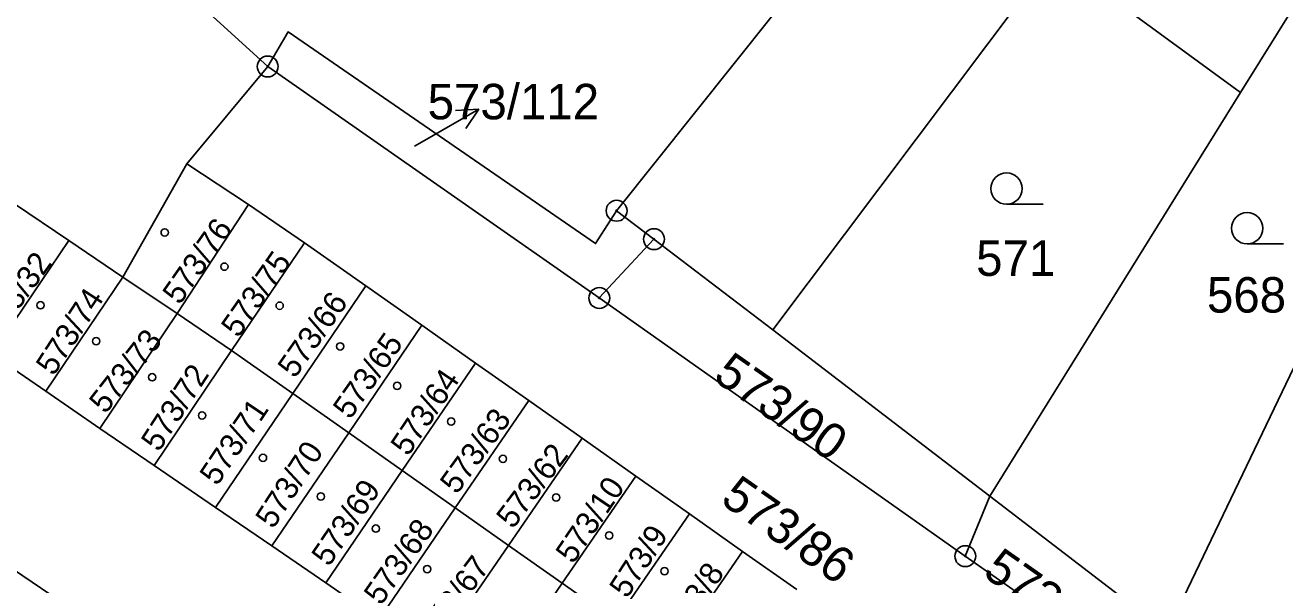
# Model space of a CAD drawing. Extents: x -776701 to -776081, y -974398 to -973771.
# Drawn here: x -776402.9 to -776342.5, y -974028.3 to -974001.5 of the extents above; entities that cross this region are included whole.
import ezdxf

# ---------------------------------------------------------------- set-up
doc = ezdxf.new("R2010")
doc.units = 0
for name, color, linetype in [('Hranice parcel', 7, 'Continuous'), ('Parcelní čísla', 7, 'Continuous'), ('Pop  PČ popisy', 7, 'Continuous'), ('Značky bodu BP', 7, 'Continuous'), ('Značky budov', 7, 'Continuous'), ('Značky kultur', 7, 'Continuous')]:
    doc.layers.add(name, color=color, linetype=linetype)

msp = doc.modelspace()

# ---------------------------------------------------------------- linework, layer by layer
at = {"layer": 'Hranice parcel'}
for p, q in [((-776391.25, -974003.46), (-776398.4, -973996.95)), ((-776353.58, -973998.16), (-776367.05, -974016.08)), ((-776353.58, -973998.16), (-776344.63, -974004.7)), ((-776395.13, -974008.13), (-776391.25, -974003.46)), ((-776375.36, -974014.55), (-776391.25, -974003.46)), ((-776344.63, -974004.7), (-776356.65, -974024.04)), ((-776398.19, -974013.55), (-776395.13, -974008.13)), ((-776392.17, -974010.07), (-776395.13, -974008.13)), ((-776403.38, -974010.04), (-776400.78, -974011.8)), ((-776392.17, -974010.07), (-776395.59, -974015.3)), ((-776389.48, -974011.9), (-776392.17, -974010.07)), ((-776374.53, -974010.37), (-776372.74, -974011.73)), ((-776348.16, -974030.54), (-776338.84, -974011.12)), ((-776404.47, -974017.25), (-776400.78, -974011.8)), ((-776400.78, -974011.8), (-776398.19, -974013.55)), ((-776389.48, -974011.9), (-776392.99, -974017.06)), ((-776386.55, -974013.97), (-776389.48, -974011.9)), ((-776372.74, -974011.73), (-776375.36, -974014.55)), ((-776372.74, -974011.73), (-776367.05, -974016.08)), ((-776398.19, -974013.55), (-776401.88, -974019.02)), ((-776395.59, -974015.3), (-776398.19, -974013.55)), ((-776386.55, -974013.97), (-776390.05, -974019.13)), ((-776383.87, -974015.86), (-776386.55, -974013.97)), ((-776357.82, -974026.92), (-776375.36, -974014.55)), ((-776395.59, -974015.3), (-776399.29, -974020.8)), ((-776392.99, -974017.06), (-776395.59, -974015.3)), ((-776383.87, -974015.86), (-776387.37, -974021.01)), ((-776381.29, -974017.67), (-776383.87, -974015.86)), ((-776367.05, -974016.08), (-776356.65, -974024.04)), ((-776392.99, -974017.06), (-776396.69, -974022.57)), ((-776392.99, -974017.06), (-776390.05, -974019.13)), ((-776404.47, -974017.25), (-776401.88, -974019.02)), ((-776381.29, -974017.67), (-776384.81, -974022.82)), ((-776378.74, -974019.46), (-776381.29, -974017.67)), ((-776401.88, -974019.02), (-776399.29, -974020.8)), ((-776390.05, -974019.13), (-776393.75, -974024.59)), ((-776390.05, -974019.13), (-776387.37, -974021.01)), ((-776378.74, -974019.46), (-776382.26, -974024.61)), ((-776376.18, -974021.27), (-776378.74, -974019.46)), ((-776399.29, -974020.8), (-776396.69, -974022.57)), ((-776387.37, -974021.01), (-776391.06, -974026.43)), ((-776387.37, -974021.01), (-776384.81, -974022.82)), ((-776376.18, -974021.27), (-776379.71, -974026.41)), ((-776373.61, -974023.08), (-776376.18, -974021.27)), ((-776396.69, -974022.57), (-776393.75, -974024.59)), ((-776384.81, -974022.82), (-776388.47, -974028.2)), ((-776384.81, -974022.82), (-776382.26, -974024.61)), ((-776373.61, -974023.08), (-776377.14, -974028.21)), ((-776371.04, -974024.89), (-776373.61, -974023.08)), ((-776357.82, -974026.92), (-776356.65, -974024.04)), ((-776356.65, -974024.04), (-776348.16, -974030.54)), ((-776393.75, -974024.59), (-776391.06, -974026.43)), ((-776382.26, -974024.61), (-776385.91, -974029.95)), ((-776382.26, -974024.61), (-776379.71, -974026.41)), ((-776371.04, -974024.89), (-776374.57, -974030.02)), ((-776368.49, -974026.69), (-776371.04, -974024.89)), ((-776391.06, -974026.43), (-776388.47, -974028.2)), ((-776379.71, -974026.41), (-776383.35, -974031.71)), ((-776379.71, -974026.41), (-776377.14, -974028.21)), ((-776368.49, -974026.69), (-776372.03, -974031.81)), ((-776365.9, -974028.51), (-776368.49, -974026.69)), ((-776348.94, -974033.12), (-776357.82, -974026.92)), ((-776400.79, -974029.35), (-776403.43, -974027.56)), ((-776388.47, -974028.2), (-776385.91, -974029.95)), ((-776380.76, -974033.48), (-776377.14, -974028.21)), ((-776377.14, -974028.21), (-776374.57, -974030.02))]:
    msp.add_line(p, q, dxfattribs=at)
for points in [[(-776337.75, -973970.3), (-776338.32, -973970.69), (-776348.3, -973977.53), (-776374.53, -974010.37)], [(-776336.89, -973994.45), (-776339.24, -973996.03), (-776344.63, -974004.7)], [(-776391.25, -974003.46), (-776390.27, -974001.8), (-776375.54, -974011.94), (-776374.53, -974010.37)]]:
    msp.add_lwpolyline(points, dxfattribs=at)
at = {"layer": 'Pop  PČ popisy'}
for p, q in [((-776383.73, -974007), (-776381.131, -974005.5)), ((-776381.131, -974005.5), (-776382.249, -974005.567)), ((-776381.131, -974005.5), (-776381.748, -974006.434)), ((-776384.22, -974007.28), (-776383.73, -974007))]:
    msp.add_line(p, q, dxfattribs=at)
at = {"layer": 'Značky bodu BP'}
for centre, radius in [((-776391.25, -974003.46), 0.5), ((-776391.25, -974003.46), 0.0303), ((-776374.53, -974010.37), 0.5), ((-776374.53, -974010.37), 0.0303), ((-776372.74, -974011.73), 0.5), ((-776372.74, -974011.73), 0.0303), ((-776375.36, -974014.55), 0.5), ((-776375.36, -974014.55), 0.0303), ((-776357.82, -974026.92), 0.5), ((-776357.82, -974026.92), 0.0303)]:
    msp.add_circle(centre, radius, dxfattribs=at)
at = {"layer": 'Značky budov'}
for centre in [(-776396.187, -974011.409), (-776393.327, -974013.049), (-776402.137, -974014.899), (-776390.677, -974014.919), (-776399.467, -974016.619), (-776387.777, -974016.869), (-776396.787, -974018.349), (-776385.047, -974018.759), (-776394.397, -974020.179), (-776382.457, -974020.469), (-776391.477, -974022.209), (-776379.977, -974022.259), (-776388.707, -974024.059), (-776377.427, -974024.109), (-776386.067, -974025.599), (-776374.887, -974025.929), (-776383.607, -974027.539), (-776372.237, -974027.639)]:
    msp.add_circle(centre, 0.175, dxfattribs=at)
at = {"layer": 'Značky kultur'}
for p, q in [((-776355.843, -974010.06), (-776354.093, -974010.06)), ((-776344.313, -974011.96), (-776342.563, -974011.96))]:
    msp.add_line(p, q, dxfattribs=at)
for centre in [(-776355.843, -974009.31), (-776344.313, -974011.21)]:
    msp.add_circle(centre, 0.75, dxfattribs=at)

# ---------------------------------------------------------------- texts
at = {"layer": 'Parcelní čísla'}
for s, p in [('573/112', (-776383.586, -974005.99)), ('571', (-776357.3, -974013.49)), ('568', (-776346.24, -974015.25))]:
    msp.add_text(s, height=1.7, dxfattribs=at).set_placement(p)
for s, height, rotation, p in [('573/76', 1.1, 55, (-776395.469, -974014.925)), ('573/75', 1.1, 55, (-776392.659, -974016.505)), ('573/32', 1.1, 54, (-776404.195, -974016.513)), ('573/74', 1.1, 57, (-776401.508, -974018.329)), ('573/66', 1.1, 55, (-776389.949, -974018.445)), ('573/73', 1.1, 52, (-776399.026, -974020.148)), ('573/65', 1.1, 55, (-776387.299, -974020.415)), ('573/90', 1.7, 325, (-776369.967, -974018.446)), ('573/72', 1.1, 57, (-776396.468, -974021.969)), ('573/64', 1.1, 56, (-776384.524, -974022.177)), ('573/71', 1.1, 56, (-776393.674, -974023.597)), ('573/63', 1.1, 54, (-776382.185, -974024.003)), ('573/70', 1.1, 57, (-776390.988, -974025.659)), ('573/62', 1.1, 53, (-776379.5, -974025.66)), ('573/86', 1.7, 325, (-776369.617, -974024.346)), ('573/69', 1.1, 56, (-776388.314, -974027.467)), ('573/10', 1.1, 56, (-776376.614, -974027.337)), ('573/68', 1.1, 55, (-776385.819, -974029.325)), ('573/9', 1.1, 57, (-776374.028, -974028.989)), ('573/91', 1.7, 325, (-776357.047, -974027.826)), ('573/67', 1.1, 53, (-776383.26, -974031.04)), ('573/8', 1.1, 56, (-776371.384, -974030.767))]:
    msp.add_text(s, height=height, rotation=rotation, dxfattribs=at).set_placement(p)

doc.saveas('drawing.dxf')
